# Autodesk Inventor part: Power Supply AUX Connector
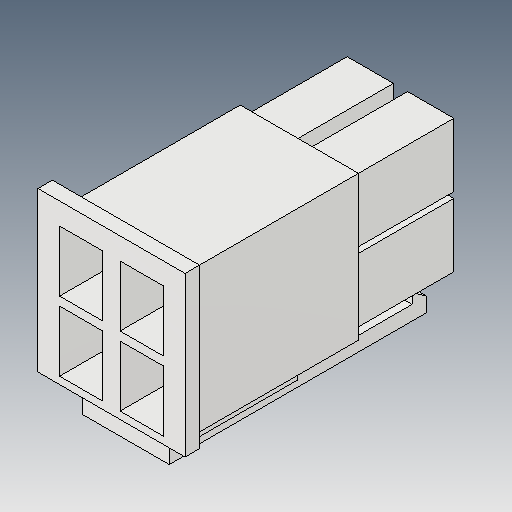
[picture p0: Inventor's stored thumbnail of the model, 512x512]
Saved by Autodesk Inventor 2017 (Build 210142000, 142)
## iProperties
Created: 2005-12
Part Number: Power Supply AUX Connector
Material: Generic
Document SubType Name: Modeling
Designer: DanielSeverino
Density: 1 g/cm^3
Appearance: Default
Author: DanielSeverino
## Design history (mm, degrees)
feature "Solid1"
body "Solid2"
